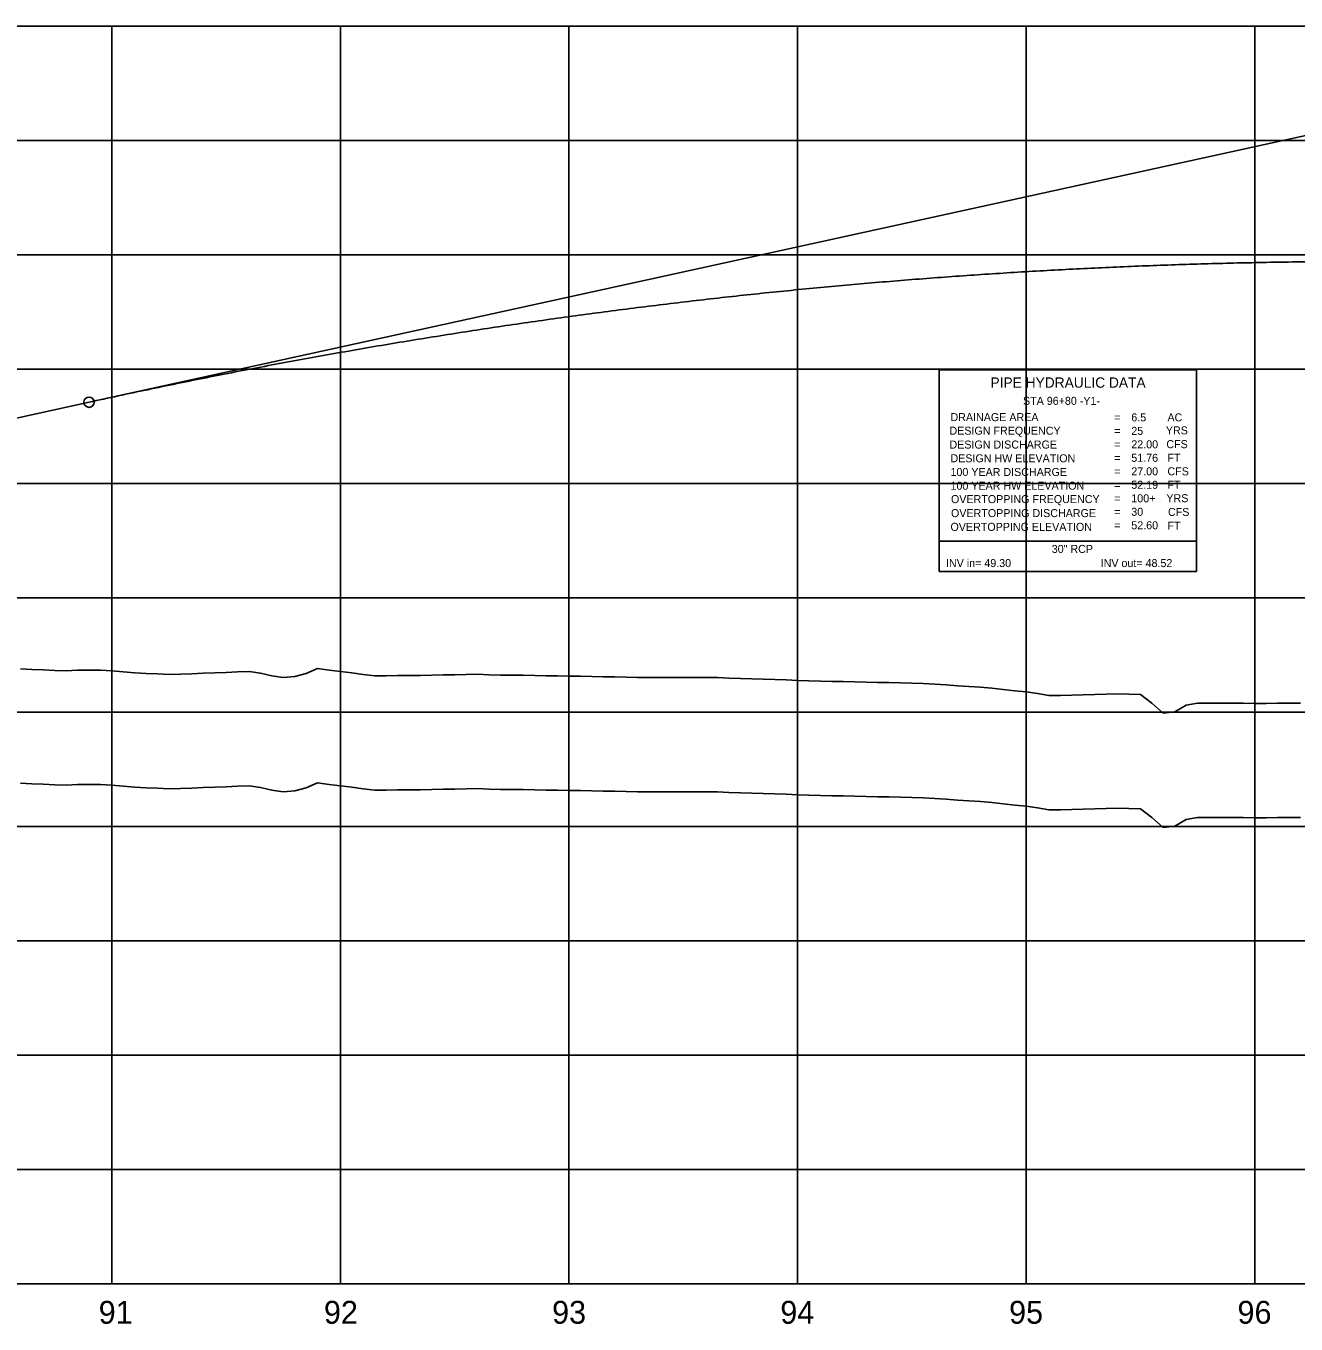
# Model space of a CAD drawing. Extents: x 2345490 to 2445302, y 465165 to 573888.
# Drawn here: x 2389384 to 2389940, y 557766 to 558334 of the extents above; entities that cross this region are included whole.
import ezdxf

# ---------------------------------------------------------------- set-up
doc = ezdxf.new("R2010")
doc.units = 0
for name, color, linetype in [('Old_Level_1', 7, 'Continuous'), ('Old_Level_2', 7, 'Continuous'), ('Old_Level_4', 7, 'Continuous'), ('Old_Level_57', 7, 'Continuous'), ('Old_Level_62', 7, 'Continuous'), ('Old_Level_63', 7, 'Continuous')]:
    doc.layers.add(name, color=color, linetype=linetype)

msp = doc.modelspace()

# ---------------------------------------------------------------- linework, layer by layer
at = {"layer": 'Old_Level_1'}
for points in [[(2389381.5425, 558002.99575), (2389386.5425, 558002.7675), (2389391.5425, 558002.5395), (2389396.5425, 558002.31125), (2389401.5425, 558002.15925), (2389406.5425, 558002.37775), (2389411.5425, 558002.449), (2389416.5425, 558002.52025), (2389421.5425, 558002.22925), (2389426.5425, 558001.71875), (2389431.5425, 558001.29225), (2389436.5425, 558001.06275), (2389441.5425, 558000.8335), (2389446.5425, 558000.604), (2389451.5425, 558000.64475), (2389456.5425, 558000.89975), (2389461.5425, 558001.09525), (2389466.5425, 558001.291), (2389471.5425, 558001.4865), (2389476.5425, 558001.682), (2389481.5425, 558001.87775), (2389486.5425, 558001.20975), (2389491.5425, 557999.98425), (2389496.5425, 557999.304), (2389501.5425, 557999.6535), (2389506.5425, 558001.0615), (2389511.5425, 558003.237), (2389516.5425, 558002.43), (2389521.5425, 558001.827), (2389526.5425, 558001.22375), (2389531.5425, 558000.62075), (2389536.5425, 558000.0175), (2389541.5425, 557999.96125), (2389546.5425, 558000.05), (2389551.5425, 558000.11375), (2389556.5425, 558000.1775), (2389561.5425, 558000.2415), (2389566.5425, 558000.3385), (2389571.5425, 558000.453), (2389576.5425, 558000.5675), (2389581.5425, 558000.67825), (2389586.5425, 558000.446), (2389591.5425, 558000.2805), (2389596.5425, 558000.238), (2389601.5425, 558000.1955), (2389606.5425, 558000.11675), (2389611.5425, 558000.02675), (2389616.5425, 557999.937), (2389621.5425, 557999.847), (2389626.5425, 557999.757), (2389631.5425, 557999.667), (2389636.5425, 557999.577), (2389641.5425, 557999.487), (2389646.5425, 557999.397), (2389651.5425, 557999.307), (2389656.5425, 557999.217), (2389661.5425, 557999.226), (2389666.5425, 557999.23525), (2389671.5425, 557999.2445), (2389676.5425, 557999.25375), (2389681.5425, 557999.263), (2389686.5425, 557999.17775), (2389691.5425, 557999.00875), (2389696.5425, 557998.83975), (2389701.5425, 557998.67075), (2389706.5425, 557998.50175), (2389711.5425, 557998.33275), (2389716.5425, 557998.16375), (2389721.5425, 557997.99475), (2389726.5425, 557997.82575), (2389731.5425, 557997.66125), (2389736.5425, 557997.548), (2389741.5425, 557997.4365), (2389746.5425, 557997.325), (2389751.5425, 557997.21375), (2389756.5425, 557997.10225), (2389761.5425, 557996.99075), (2389766.5425, 557996.8795), (2389771.5425, 557996.768), (2389776.5425, 557996.65675), (2389781.5425, 557996.39), (2389786.5425, 557996.02925), (2389791.5425, 557995.6685), (2389796.5425, 557995.30775), (2389801.5425, 557994.947), (2389806.5425, 557994.58625), (2389811.5425, 557994.03675), (2389816.5425, 557993.48175), (2389821.5425, 557992.92675)], [(2389821.5425, 557992.92675), (2389826.5425, 557992.31125), (2389831.5425, 557991.4145), (2389836.5425, 557991.436), (2389841.5425, 557991.561), (2389846.5425, 557991.686), (2389851.5425, 557991.811), (2389856.5425, 557991.93575), (2389861.5425, 557992.06075), (2389866.5425, 557991.93975), (2389871.5425, 557991.81), (2389876.5425, 557988.07675), (2389881.5425, 557983.58525), (2389886.5425, 557984.2855), (2389891.5425, 557987.15425), (2389896.5425, 557988.0095), (2389901.5425, 557988.03675), (2389906.5425, 557988.0545), (2389911.5425, 557988.00425), (2389916.5425, 557987.94775), (2389921.5425, 557987.933), (2389926.5425, 557987.9295), (2389931.5425, 557987.9445), (2389936.5425, 557987.97075), (2389941.5425, 557987.997)]]:
    msp.add_lwpolyline(points, dxfattribs=at)
at = {"layer": 'Old_Level_2'}
for p, q in [((2389411.5425, 558169.65525), (2390048.8565, 558309.32425)), ((2389121.5425, 558106.101), (2389411.5425, 558169.65525))]:
    msp.add_line(p, q, dxfattribs=at)
msp.add_circle((2389411.5425, 558169.65525), 2.25, dxfattribs=at)
msp.add_spline([(2389411.5425, 558169.65525), (2389437.1425, 558175.13775), (2389462.7425, 558180.36475), (2389488.3425, 558185.336), (2389513.9425, 558190.052), (2389539.5425, 558194.51225), (2389565.1425, 558198.717), (2389590.7425, 558202.666), (2389616.3425, 558206.3595), (2389641.9425, 558209.7975), (2389667.5425, 558212.98), (2389693.1425, 558215.90675), (2389718.7425, 558218.57825), (2389744.3425, 558220.994), (2389769.9425, 558223.154), (2389795.5425, 558225.05875), (2389821.1425, 558226.70775), (2389846.7425, 558228.10125), (2389872.3425, 558229.239), (2389897.9425, 558230.12125), (2389923.5425, 558230.74825), (2389949.1425, 558231.11925), (2389974.7425, 558231.235), (2390000.3425, 558231.095), (2390025.9425, 558230.6995), (2390051.5425, 558230.0485), (2390077.1425, 558229.14175), (2390102.7425, 558227.97975), (2390128.3425, 558226.562), (2390153.9425, 558224.8885), (2390179.5425, 558222.95975), (2390205.1425, 558220.77525), (2390230.7425, 558218.33525), (2390256.3425, 558215.6395), (2390281.9425, 558212.6885), (2390307.5425, 558209.48175), (2390333.1425, 558206.0195), (2390358.7425, 558202.3015), (2390384.3425, 558198.328), (2390409.9425, 558194.09925), (2390435.5425, 558189.6145), (2390461.1425, 558184.8745), (2390486.7425, 558179.87875), (2390512.3425, 558174.6275), (2390537.94275, 558169.12075), (2390563.54275, 558163.35825), (2390589.14275, 558157.34025), (2390614.74275, 558151.06675), (2390640.34275, 558144.53775), (2390665.94275, 558137.753), (2390691.54275, 558130.713)], degree=3, dxfattribs=at)
at = {"layer": 'Old_Level_4'}
for p, q in [((2389783.55325, 558183.8278), (2389896.05325, 558183.8278)), ((2389783.55325, 558108.8278), (2389783.55325, 558183.8278)), ((2389896.05325, 558183.8278), (2389896.05325, 558108.8278)), ((2389896.05325, 558108.8278), (2389783.55325, 558108.8278))]:
    msp.add_line(p, q, dxfattribs=at)
msp.add_lwpolyline([(2389783.55325, 558108.8278), (2389896.05325, 558108.8278), (2389896.05325, 558095.6128), (2389783.55325, 558095.6128)], close=True, dxfattribs=at)
at = {"layer": 'Old_Level_57'}
for p, q in [((2381271.54275, 558334.11325), (2393041.55275, 558334.11325)), ((2389421.54225, 557784.21325), (2389421.54225, 558334.21325)), ((2389421.54225, 557784.11325), (2389421.54225, 558334.11325)), ((2389521.54225, 557784.21325), (2389521.54225, 558334.21325)), ((2389521.54225, 557784.11325), (2389521.54225, 558334.11325)), ((2389621.54225, 557784.21325), (2389621.54225, 558334.21325)), ((2389621.54225, 557784.11325), (2389621.54225, 558334.11325)), ((2389721.54225, 557784.21325), (2389721.54225, 558334.21325)), ((2389721.54225, 557784.11325), (2389721.54225, 558334.11325)), ((2389821.54225, 557784.21325), (2389821.54225, 558334.21325)), ((2389821.54225, 557784.11325), (2389821.54225, 558334.11325)), ((2389921.54225, 557784.21325), (2389921.54225, 558334.21325)), ((2389921.54225, 557784.11325), (2389921.54225, 558334.11325)), ((2381271.54275, 558284.11325), (2393041.55275, 558284.11325)), ((2381271.54275, 558234.11325), (2393041.55275, 558234.11325)), ((2381271.54275, 558184.11325), (2393041.55275, 558184.11325)), ((2381271.54275, 558134.11325), (2393041.55275, 558134.11325)), ((2381271.54275, 558084.11325), (2393041.55275, 558084.11325)), ((2381271.5425, 558034.11325), (2393041.55275, 558034.11325)), ((2381271.54275, 557984.11325), (2393041.55275, 557984.11325)), ((2381271.5425, 557934.11325), (2393041.55275, 557934.11325)), ((2381271.54275, 557884.11325), (2393041.55275, 557884.11325)), ((2381271.5425, 557834.11325), (2393041.55275, 557834.11325)), ((2381271.54275, 557784.11325), (2393041.55275, 557784.11325))]:
    msp.add_line(p, q, dxfattribs=at)
at = {"layer": 'Old_Level_62'}
for points in [[(2389381.5425, 558053.00175), (2389386.5425, 558052.7735), (2389391.5425, 558052.5455), (2389396.5425, 558052.31725), (2389401.5425, 558052.16525), (2389406.5425, 558052.38375), (2389411.5425, 558052.455), (2389416.5425, 558052.52625), (2389421.5425, 558052.23525), (2389426.5425, 558051.72475), (2389431.5425, 558051.29825), (2389436.5425, 558051.06875), (2389441.5425, 558050.8395), (2389446.5425, 558050.61), (2389451.5425, 558050.65075), (2389456.5425, 558050.90575), (2389461.5425, 558051.10125), (2389466.5425, 558051.297), (2389471.5425, 558051.4925), (2389476.5425, 558051.688), (2389481.5425, 558051.88375), (2389486.5425, 558051.21575), (2389491.5425, 558049.99025), (2389496.5425, 558049.31), (2389501.5425, 558049.6595), (2389506.5425, 558051.0675), (2389511.5425, 558053.243), (2389516.5425, 558052.436), (2389521.5425, 558051.833), (2389526.5425, 558051.22975), (2389531.5425, 558050.62675), (2389536.5425, 558050.0235), (2389541.5425, 558049.96725), (2389546.5425, 558050.056), (2389551.5425, 558050.11975), (2389556.5425, 558050.1835), (2389561.5425, 558050.2475), (2389566.5425, 558050.3445), (2389571.5425, 558050.459), (2389576.5425, 558050.5735), (2389581.5425, 558050.68425), (2389586.5425, 558050.452), (2389591.5425, 558050.2865), (2389596.5425, 558050.244), (2389601.5425, 558050.2015), (2389606.5425, 558050.12275), (2389611.5425, 558050.03275), (2389616.5425, 558049.943), (2389621.5425, 558049.853), (2389626.5425, 558049.763), (2389631.5425, 558049.673), (2389636.5425, 558049.583), (2389641.5425, 558049.493), (2389646.5425, 558049.403), (2389651.5425, 558049.313), (2389656.5425, 558049.223), (2389661.5425, 558049.232), (2389666.5425, 558049.24125), (2389671.5425, 558049.2505), (2389676.5425, 558049.25975), (2389681.5425, 558049.269), (2389686.5425, 558049.18375), (2389691.5425, 558049.01475), (2389696.5425, 558048.84575), (2389701.5425, 558048.67675), (2389706.5425, 558048.50775), (2389711.5425, 558048.33875), (2389716.5425, 558048.16975), (2389721.5425, 558048.00075), (2389726.5425, 558047.83175), (2389731.5425, 558047.66725), (2389736.5425, 558047.554), (2389741.5425, 558047.4425), (2389746.5425, 558047.331), (2389751.5425, 558047.21975), (2389756.5425, 558047.10825), (2389761.5425, 558046.99675), (2389766.5425, 558046.8855), (2389771.5425, 558046.774), (2389776.5425, 558046.66275), (2389781.5425, 558046.396), (2389786.5425, 558046.03525), (2389791.5425, 558045.6745), (2389796.5425, 558045.31375), (2389801.5425, 558044.953), (2389806.5425, 558044.59225), (2389811.5425, 558044.04275), (2389816.5425, 558043.48775), (2389821.5425, 558042.93275)], [(2389821.5425, 558042.93275), (2389826.5425, 558042.31725), (2389831.5425, 558041.4205), (2389836.5425, 558041.442), (2389841.5425, 558041.567), (2389846.5425, 558041.692), (2389851.5425, 558041.817), (2389856.5425, 558041.94175), (2389861.5425, 558042.06675), (2389866.5425, 558041.94575), (2389871.5425, 558041.816), (2389876.5425, 558038.08275), (2389881.5425, 558033.59125), (2389886.5425, 558034.2915), (2389891.5425, 558037.16025), (2389896.5425, 558038.0155), (2389901.5425, 558038.04275), (2389906.5425, 558038.0605), (2389911.5425, 558038.01025), (2389916.5425, 558037.95375), (2389921.5425, 558037.939), (2389926.5425, 558037.9355), (2389931.5425, 558037.9505), (2389936.5425, 558037.97675), (2389941.5425, 558038.003)]]:
    msp.add_lwpolyline(points, dxfattribs=at)
at = {"layer": 'Old_Level_63'}
msp.add_line((2381321.5425, 557784.113), (2393019.104, 557784.113), dxfattribs=at)

# ---------------------------------------------------------------- texts
at = {"layer": 'Old_Level_1'}
for s, p in [('91', (2389415.7685, 557766.613)), ('92', (2389514.31675, 557766.613)), ('93', (2389614.1515, 557766.613)), ('94', (2389713.994, 557766.613)), ('95', (2389814.0865, 557766.613)), ('96', (2389914.0275, 557766.613))]:
    msp.add_text(s, height=10.000001, dxfattribs=at).set_placement(p)
at = {"layer": 'Old_Level_4'}
for s, height, p in [('PIPE HYDRAULIC DATA', 4.49985, (2389805.95325, 558176.0028)), ('STA 96+80 -Y1-', 3.4998, (2389820.174, 558168.5023)), ('DRAINAGE AREA', 3.49995, (2389788.45325, 558161.3778)), ('6.5', 3.49995, (2389867.56375, 558161.2773)), ('AC', 3.49995, (2389883.37825, 558161.2778)), ('DESIGN FREQUENCY', 3.49995, (2389788.00325, 558155.4528)), ('=        ', 3.49995, (2389860.10325, 558161.2778)), ('25', 3.49995, (2389867.56375, 558155.3773)), ('YRS', 3.49995, (2389882.67825, 558155.5778)), ('=        ', 3.49995, (2389860.10325, 558155.3778)), ('22.00', 3.49995, (2389867.56375, 558149.4773)), ('CFS', 3.49995, (2389882.90325, 558149.5528)), ('DESIGN DISCHARGE', 3.49995, (2389788.00325, 558149.3778)), ('=        ', 3.49995, (2389860.10325, 558149.4778)), ('DESIGN HW ELEVATION', 3.49995, (2389788.45325, 558143.3778)), ('=        ', 3.49995, (2389860.10325, 558143.5778)), ('51.76', 3.49995, (2389867.56375, 558143.5773)), ('FT', 3.49995, (2389883.37825, 558143.5778)), ('100 YEAR DISCHARGE', 3.49995, (2389788.45325, 558137.3778)), ('=        ', 3.49995, (2389860.10325, 558137.6778)), ('27.00', 3.49995, (2389867.56375, 558137.6773)), ('CFS', 3.49995, (2389883.37825, 558137.6778)), ('100 YEAR HW ELEVATION', 3.49995, (2389788.45325, 558131.3778)), ('=        ', 3.49995, (2389860.10325, 558131.7778)), ('52.19', 3.49995, (2389867.56375, 558131.77755)), ('FT', 3.49995, (2389883.37825, 558131.7778)), ('OVERTOPPING FREQUENCY', 3.49995, (2389788.67825, 558125.5278)), ('=        ', 3.49995, (2389860.10325, 558125.8778)), ('100+', 3.49995, (2389867.56375, 558125.87755)), ('YRS', 3.49995, (2389882.90325, 558125.9278)), ('OVERTOPPING DISCHARGE', 3.49995, (2389788.67825, 558119.4028)), ('=        ', 3.49995, (2389860.10325, 558119.9778)), ('30', 3.49995, (2389867.56375, 558119.97755)), ('CFS', 3.49995, (2389883.60325, 558119.9028)), ('OVERTOPPING ELEVATION', 3.49995, (2389788.45325, 558113.3778)), ('=        ', 3.49995, (2389860.10325, 558114.0778)), ('52.60', 3.49995, (2389867.56375, 558114.07755)), ('FT', 3.49995, (2389883.37825, 558113.8778)), ('30" RCP', 3.4998, (2389832.759, 558103.72555)), ('INV in= 49.30', 3.4998, (2389786.48575, 558097.5398)), ('INV out= 48.52', 3.4998, (2389854.1625, 558097.5398))]:
    msp.add_text(s, height=height, dxfattribs=at).set_placement(p)

doc.saveas('drawing.dxf')
